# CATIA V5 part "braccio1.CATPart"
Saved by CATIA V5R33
Part number: braccio1
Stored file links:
  C:\Users\Ryzen5700u\Desktop\robot_cicloidale_singolo\Assieme_robot_cicloidale_singolo\braccio1.CATPart

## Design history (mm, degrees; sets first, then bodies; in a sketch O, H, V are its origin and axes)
Body1 "Solido1" (main body)
  Solid1: solid without history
